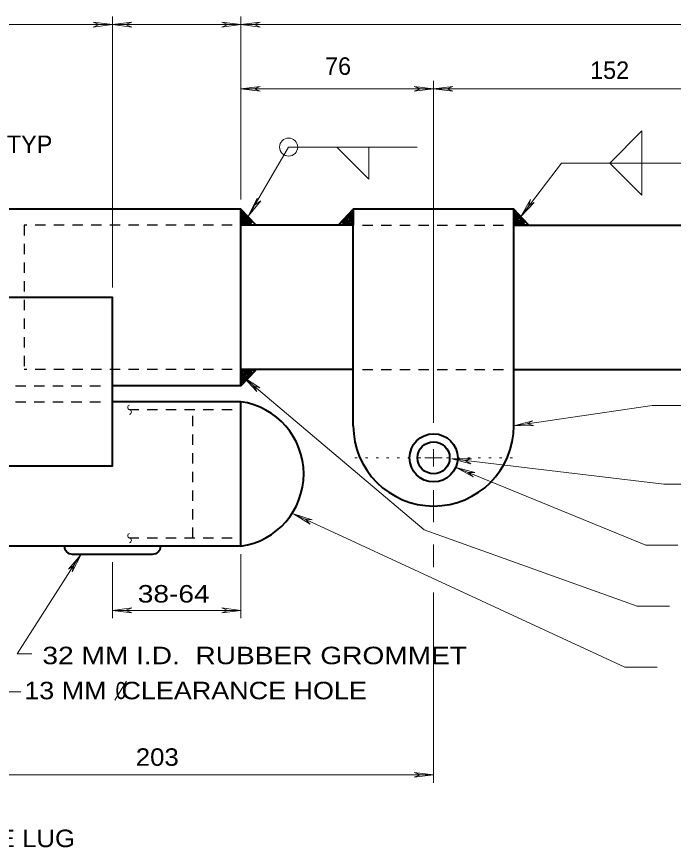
# Model space of a CAD drawing. Extents: x 312583 to 312854, y 144419 to 144597.
# Drawn here: x 312792.77 to 312821.27, y 144484.6 to 144520.68 of the extents above; entities that cross this region are included whole.
import ezdxf
from ezdxf.enums import TextEntityAlignment as Align

# ---------------------------------------------------------------- set-up
doc = ezdxf.new("R2010")
doc.units = 0
doc.header["$LTSCALE"] = 0.3
doc.linetypes.add('DOTTED', pattern=[1.5, 0.3, -1.2])
doc.linetypes.add('SHORT_DASHED', pattern=[2.7, 1.5, -1.2])
doc.layers.add('1', color=7, linetype='Continuous', lineweight=13)

msp = doc.modelspace()

# ---------------------------------------------------------------- linework, layer by layer
at = {"layer": '1'}
for p, q in [((312796.9296, 144508.9192), (312796.9296, 144520.6799)), ((312802.5033, 144512.7296), (312802.5033, 144520.6799)), ((312796.0863, 144520.4346), (312796.3546, 144520.3349)), ((312796.9296, 144520.3349), (312796.0863, 144520.4346)), ((312796.0863, 144520.2276), (312796.3546, 144520.3349)), ((312796.9296, 144520.3349), (312796.0863, 144520.2276)), ((312796.9296, 144520.3349), (312797.7653, 144520.4346)), ((312796.9296, 144520.3349), (312797.7653, 144520.2276)), ((312797.7653, 144520.4346), (312797.4969, 144520.3349)), ((312797.7653, 144520.2276), (312797.4969, 144520.3349)), ((312801.6676, 144520.4346), (312801.9283, 144520.3349)), ((312802.5033, 144520.3349), (312801.6676, 144520.4346)), ((312801.6676, 144520.2276), (312801.9283, 144520.3349)), ((312802.5033, 144520.3349), (312801.6676, 144520.2276)), ((312802.5033, 144520.3349), (312803.3389, 144520.4346)), ((312802.5033, 144520.3349), (312827.5963, 144520.3349)), ((312802.5033, 144520.3349), (312803.3389, 144520.2276)), ((312803.3389, 144520.4346), (312803.0783, 144520.3349)), ((312803.3389, 144520.2276), (312803.0783, 144520.3349)), ((312810.8676, 144503.0312), (312810.8676, 144517.8892)), ((312802.5033, 144517.5442), (312803.3389, 144517.6439)), ((312810.8676, 144517.5442), (312802.5033, 144517.5442)), ((312802.5033, 144517.5442), (312803.3389, 144517.4446)), ((312803.3389, 144517.6439), (312803.0783, 144517.5442)), ((312803.3389, 144517.4446), (312803.0783, 144517.5442)), ((312810.0243, 144517.6439), (312810.2926, 144517.5442)), ((312810.8676, 144517.5442), (312810.0243, 144517.6439)), ((312810.0243, 144517.4446), (312810.2926, 144517.5442)), ((312810.8676, 144517.5442), (312810.0243, 144517.4446)), ((312810.8676, 144517.5442), (312811.7033, 144517.6439)), ((312810.8676, 144517.5442), (312827.5963, 144517.5442)), ((312810.8676, 144517.5442), (312811.7033, 144517.4446)), ((312811.7033, 144517.6439), (312811.4349, 144517.5442)), ((312811.7033, 144517.4446), (312811.4349, 144517.5442)), ((312804.5733, 144515.0142), (312802.8329, 144512.0319)), ((312810.1469, 144515.0142), (312804.5733, 144515.0142)), ((312816.4183, 144514.3166), (312814.6473, 144512.0012)), ((312821.9996, 144514.3166), (312816.4183, 144514.3166)), ((312802.8329, 144512.0319), (312803.2009, 144512.7986)), ((312803.2009, 144512.7986), (312803.1396, 144512.5149)), ((312814.6473, 144512.0012), (312815.0766, 144512.7372)), ((312815.0766, 144512.7372), (312814.9923, 144512.4612)), ((312802.8329, 144512.0319), (312803.3696, 144512.6836)), ((312803.3696, 144512.6836), (312803.1396, 144512.5149)), ((312814.6473, 144512.0012), (312815.2376, 144512.6069)), ((312815.2376, 144512.6069), (312814.9923, 144512.4612)), ((312810.4536, 144498.3852), (312802.6183, 144505.0246)), ((312802.6183, 144505.0246), (312803.1933, 144504.3959)), ((312802.6183, 144505.0246), (312803.3236, 144504.5569)), ((312803.1933, 144504.3959), (312803.0553, 144504.6489)), ((312803.3236, 144504.5569), (312803.0553, 144504.6489)), ((312814.3483, 144502.9086), (312815.1686, 144503.1232)), ((312815.1686, 144503.1232), (312814.9233, 144502.9852)), ((312815.1993, 144502.9162), (312814.9233, 144502.9852)), ((312814.3483, 144502.9086), (312815.1993, 144502.9162)), ((312810.8676, 144501.5132), (312810.8676, 144501.8889)), ((312810.8676, 144501.5132), (312810.4919, 144501.5132)), ((312810.8676, 144501.5132), (312811.2356, 144501.5132)), ((312810.8676, 144501.5132), (312810.8676, 144501.1376)), ((312820.8573, 144500.3786), (312811.6649, 144501.4672)), ((312811.6649, 144501.4672), (312812.4853, 144501.2602)), ((312811.6649, 144501.4672), (312812.5083, 144501.4672)), ((312812.5083, 144501.4672), (312812.2323, 144501.3982)), ((312812.4853, 144501.2602), (312812.2323, 144501.3982)), ((312811.8413, 144501.0992), (312812.5849, 144500.6852)), ((312811.8413, 144501.0992), (312812.6616, 144500.8769)), ((312812.5849, 144500.6852), (312812.3703, 144500.8846)), ((312812.6616, 144500.8769), (312812.3703, 144500.8846)), ((312810.8676, 144500.1179), (312810.8676, 144498.7226)), ((312820.8573, 144500.3786), (312822.2526, 144500.3786)), ((312819.1706, 144492.4206), (312804.7879, 144499.0829)), ((312804.7879, 144499.0829), (312805.5086, 144498.6306)), ((312804.7879, 144499.0829), (312805.5929, 144498.8222)), ((312805.5086, 144498.6306), (312805.3093, 144498.8452)), ((312805.5929, 144498.8222), (312805.3093, 144498.8452)), ((312819.7073, 144495.0732), (312810.4536, 144498.3852)), ((312810.8676, 144497.7566), (312810.8676, 144496.7599)), ((312792.7896, 144492.9956), (312795.5573, 144497.3349)), ((312795.5726, 144497.3119), (312795.0129, 144496.6832)), ((312795.5726, 144497.3119), (312795.1739, 144496.5682)), ((312802.5033, 144497.3349), (312802.5033, 144494.5442)), ((312795.0129, 144496.6832), (312795.2429, 144496.8442)), ((312795.1739, 144496.5682), (312795.2429, 144496.8442)), ((312796.9296, 144496.9822), (312796.9296, 144494.5442)), ((312810.8676, 144495.6712), (312810.8676, 144487.3989)), ((312819.7073, 144495.0732), (312821.1026, 144495.0732)), ((312796.9296, 144494.8892), (312797.7653, 144494.9966)), ((312796.9296, 144494.8892), (312802.5033, 144494.8892)), ((312796.9296, 144494.8892), (312797.7653, 144494.7896)), ((312797.7653, 144494.9966), (312797.4969, 144494.8892)), ((312797.7653, 144494.7896), (312797.4969, 144494.8892)), ((312801.6676, 144494.9966), (312801.9283, 144494.8892)), ((312802.5033, 144494.8892), (312801.6676, 144494.9966)), ((312801.6676, 144494.7896), (312801.9283, 144494.8892)), ((312802.5033, 144494.8892), (312801.6676, 144494.7896)), ((312792.7896, 144492.9956), (312793.4336, 144492.9956)), ((312819.1706, 144492.4206), (312820.5659, 144492.4206)), ((312797.0272, 144490.9913), (312797.5409, 144491.8116)), ((312792.3449, 144491.3472), (312792.9506, 144491.3472)), ((312810.0243, 144487.8512), (312810.2926, 144487.7439)), ((312810.8676, 144487.7439), (312810.0243, 144487.8512)), ((312810.8676, 144487.7439), (312788.5653, 144487.7439)), ((312810.0243, 144487.6442), (312810.2926, 144487.7439)), ((312810.8676, 144487.7439), (312810.0243, 144487.6442))]:
    msp.add_line(p, q, dxfattribs=at)
at = {"layer": '1', "lineweight": 40}
for p, q in [((312802.5033, 144512.3156), (312769.0459, 144512.3156)), ((312802.5033, 144504.6489), (312802.5033, 144512.3156)), ((312807.3793, 144502.9086), (312807.3793, 144512.3156)), ((312814.3483, 144512.3156), (312807.3793, 144512.3156)), ((312814.3483, 144502.9086), (312814.3483, 144512.3156)), ((312807.3793, 144511.6179), (312802.5033, 144511.6179)), ((312814.3483, 144511.6179), (312827.5963, 144511.6179)), ((312807.3793, 144505.3466), (312802.5033, 144505.3466)), ((312814.3483, 144505.3466), (312827.5963, 144505.3466)), ((312802.5033, 144504.6489), (312796.9296, 144504.6489)), ((312802.5033, 144503.9512), (312796.9296, 144503.9512)), ((312802.5033, 144497.6799), (312802.5033, 144503.9512)), ((312802.5033, 144497.6799), (312769.0459, 144497.6799)), ((312795.1816, 144497.3349), (312798.6699, 144497.3349))]:
    msp.add_line(p, q, dxfattribs=at)
at = {"layer": '1', "linetype": 'SHORT_DASHED', "lineweight": 25}
for p, q in [((312802.1199, 144511.6179), (312793.0963, 144511.6179)), ((312793.0963, 144511.6179), (312793.0963, 144505.3466)), ((312807.7779, 144511.6179), (312813.9649, 144511.6179)), ((312802.1199, 144505.3466), (312793.0963, 144505.3466)), ((312807.7779, 144505.3466), (312813.9649, 144505.3466)), ((312780.5613, 144504.6489), (312796.5003, 144504.6489)), ((312780.5613, 144503.9512), (312796.5003, 144503.9512)), ((312802.1199, 144503.6062), (312797.6656, 144503.6062)), ((312800.4103, 144498.0326), (312800.4103, 144503.6062)), ((312802.1199, 144498.0326), (312797.6656, 144498.0326))]:
    msp.add_line(p, q, dxfattribs=at)
at = {"layer": '1', "linetype": 'DOTTED'}
for p, q in [((312810.3079, 144501.5132), (312807.3486, 144501.5132)), ((312811.4273, 144501.5132), (312814.4403, 144501.5132))]:
    msp.add_line(p, q, dxfattribs=at)
at = {"layer": '1'}
for points in [[(312802.5033, 144520.3349), (312796.9296, 144520.3349), (312780.2009, 144520.3349)], [(312818.5113, 144514.3166), (312819.9066, 144515.7119), (312819.9066, 144514.3166)], [(312806.6663, 144515.0142), (312808.0539, 144513.6189), (312808.0539, 144515.0142)], [(312818.5113, 144514.3166), (312819.9066, 144512.9212), (312819.9066, 144514.3166)], [(312814.3483, 144502.9086), (312820.3589, 144503.7902), (312821.7543, 144503.7902)], [(312811.8413, 144501.0992), (312820.0753, 144497.7259), (312821.4629, 144497.7259)]]:
    msp.add_lwpolyline(points, dxfattribs=at)
at = {"layer": '1', "lineweight": 40}
for points in [[(312802.5033, 144512.3156), (312802.5033, 144511.6179), (312803.1319, 144511.6562), (312802.5033, 144512.3156), (312802.5646, 144511.6869), (312802.9326, 144511.6869), (312802.5723, 144512.1622), (312802.6489, 144511.7559), (312802.9633, 144511.7406), (312802.5953, 144512.1469), (312802.6949, 144511.8172), (312802.8023, 144511.7866), (312802.7486, 144511.8402)], [(312807.3793, 144512.3156), (312807.3793, 144511.6179), (312806.7583, 144511.6562), (312807.3793, 144512.3156), (312807.3256, 144511.6869), (312806.9576, 144511.6869), (312807.3103, 144512.1622), (312807.2413, 144511.7559), (312806.9193, 144511.7406), (312807.2873, 144512.1469), (312807.1953, 144511.8172), (312807.0879, 144511.7866), (312807.1339, 144511.8402)], [(312814.3483, 144512.3156), (312814.3483, 144511.6179), (312814.9769, 144511.6562), (312814.3483, 144512.3156), (312814.4096, 144511.6869), (312814.7776, 144511.6869), (312814.4249, 144512.1622), (312814.4939, 144511.7559), (312814.8083, 144511.7406), (312814.4479, 144512.1469), (312814.5399, 144511.8172), (312814.6473, 144511.7866), (312814.6013, 144511.8402)], [(312802.5033, 144504.6489), (312802.5033, 144505.3466), (312803.1319, 144505.3159), (312802.5033, 144504.6489), (312802.5646, 144505.2776), (312802.9326, 144505.2776), (312802.5723, 144504.8022), (312802.6489, 144505.2086), (312802.9633, 144505.2316), (312802.5953, 144504.8176), (312802.6949, 144505.1472), (312802.8023, 144505.1856), (312802.7486, 144505.1242)]]:
    msp.add_lwpolyline(points, dxfattribs=at)
msp.add_lwpolyline([(312780.2009, 144501.1682), (312796.9296, 144501.1682), (312796.9296, 144508.4822), (312780.2009, 144508.4822)], close=True, dxfattribs=at)
at = {"layer": '1'}
msp.add_circle((312804.5719, 144515.0128), 0.3942, dxfattribs=at)
at = {"layer": '1', "lineweight": 40}
for radius in [1.0454, 0.697]:
    msp.add_circle((312810.8669, 144501.5139), radius, dxfattribs=at)
at = {"layer": '1'}
for centre, start, end in [((312797.6961, 144503.7058), 105, 255), ((312797.642, 144503.5039), 285, 75), ((312797.6961, 144498.13), 105, 255), ((312797.642, 144497.9281), 285, 75)]:
    msp.add_arc(centre, 0.1045, start, end, dxfattribs=at)
at = {"layer": '1', "lineweight": 40}
for centre, radius, start, end in [((312802.0599, 144500.817), 3.1675, 278.04577, 81.95422), ((312810.8669, 144502.9079), 3.4848, 180, 0), ((312795.1851, 144497.6806), 0.3485, 180, 270), ((312798.6699, 144497.6806), 0.3485, 270, 0)]:
    msp.add_arc(centre, radius, start, end, dxfattribs=at)

# ---------------------------------------------------------------- texts
at = {"layer": '1'}
for s, p in [('76', (312806.1542, 144518.1508)), ('152', (312817.6586, 144517.9736)), ('TYP', (312792.3409, 144514.754))]:
    msp.add_text(s, height=0.76, dxfattribs=at).set_placement(p)
for s, width, p in [('38-64', 1.2, (312798.0253, 144495.23)), ('32 MM I.D.  RUBBER GROMMET', 1.2, (312793.8866, 144492.5508)), ('13 MM  CLEARANCE HOLE', 1.15, (312793.0975, 144491.0281)), ('203', 1.1, (312797.9395, 144488.1379)), ('SAFETY CHAIN ANCHORAGE LUG', 1.1, (312777.0398, 144484.6059))]:
    msp.add_text(s, height=0.76, dxfattribs=dict(at, width=width)).set_placement(p)
at = {"layer": '1', "width": 0.85}
msp.add_text('0', height=0.7416, dxfattribs=at).set_placement((312797.2994, 144491.0373), align=Align.CENTER)

doc.saveas('drawing.dxf')
